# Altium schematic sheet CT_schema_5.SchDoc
size 573 x 363 mm
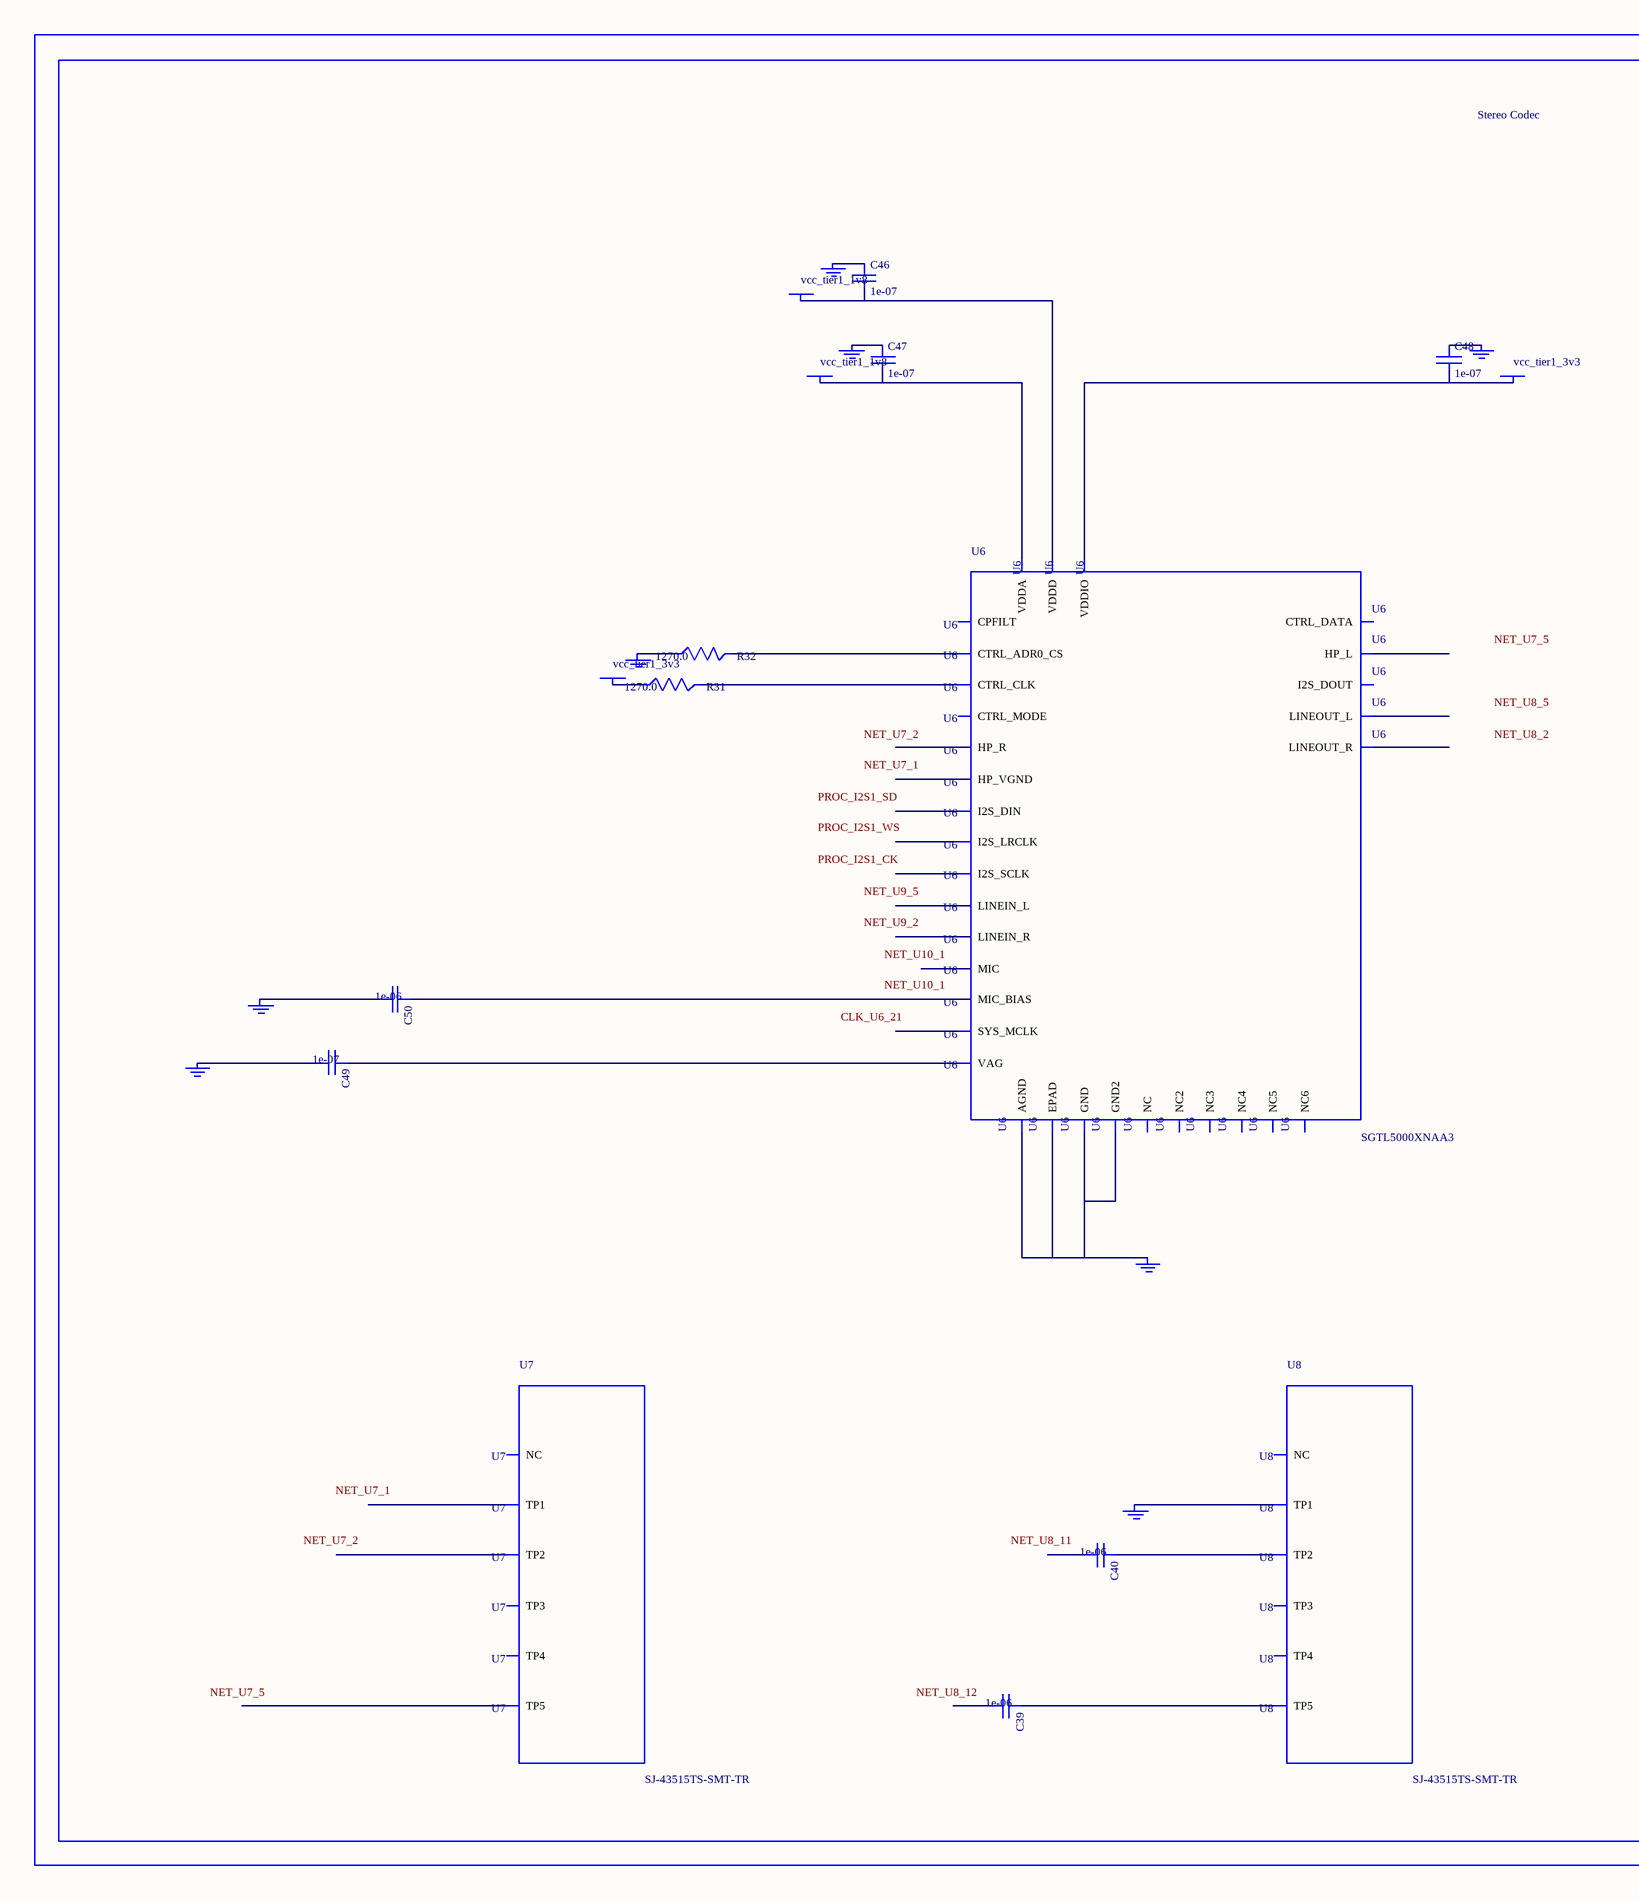
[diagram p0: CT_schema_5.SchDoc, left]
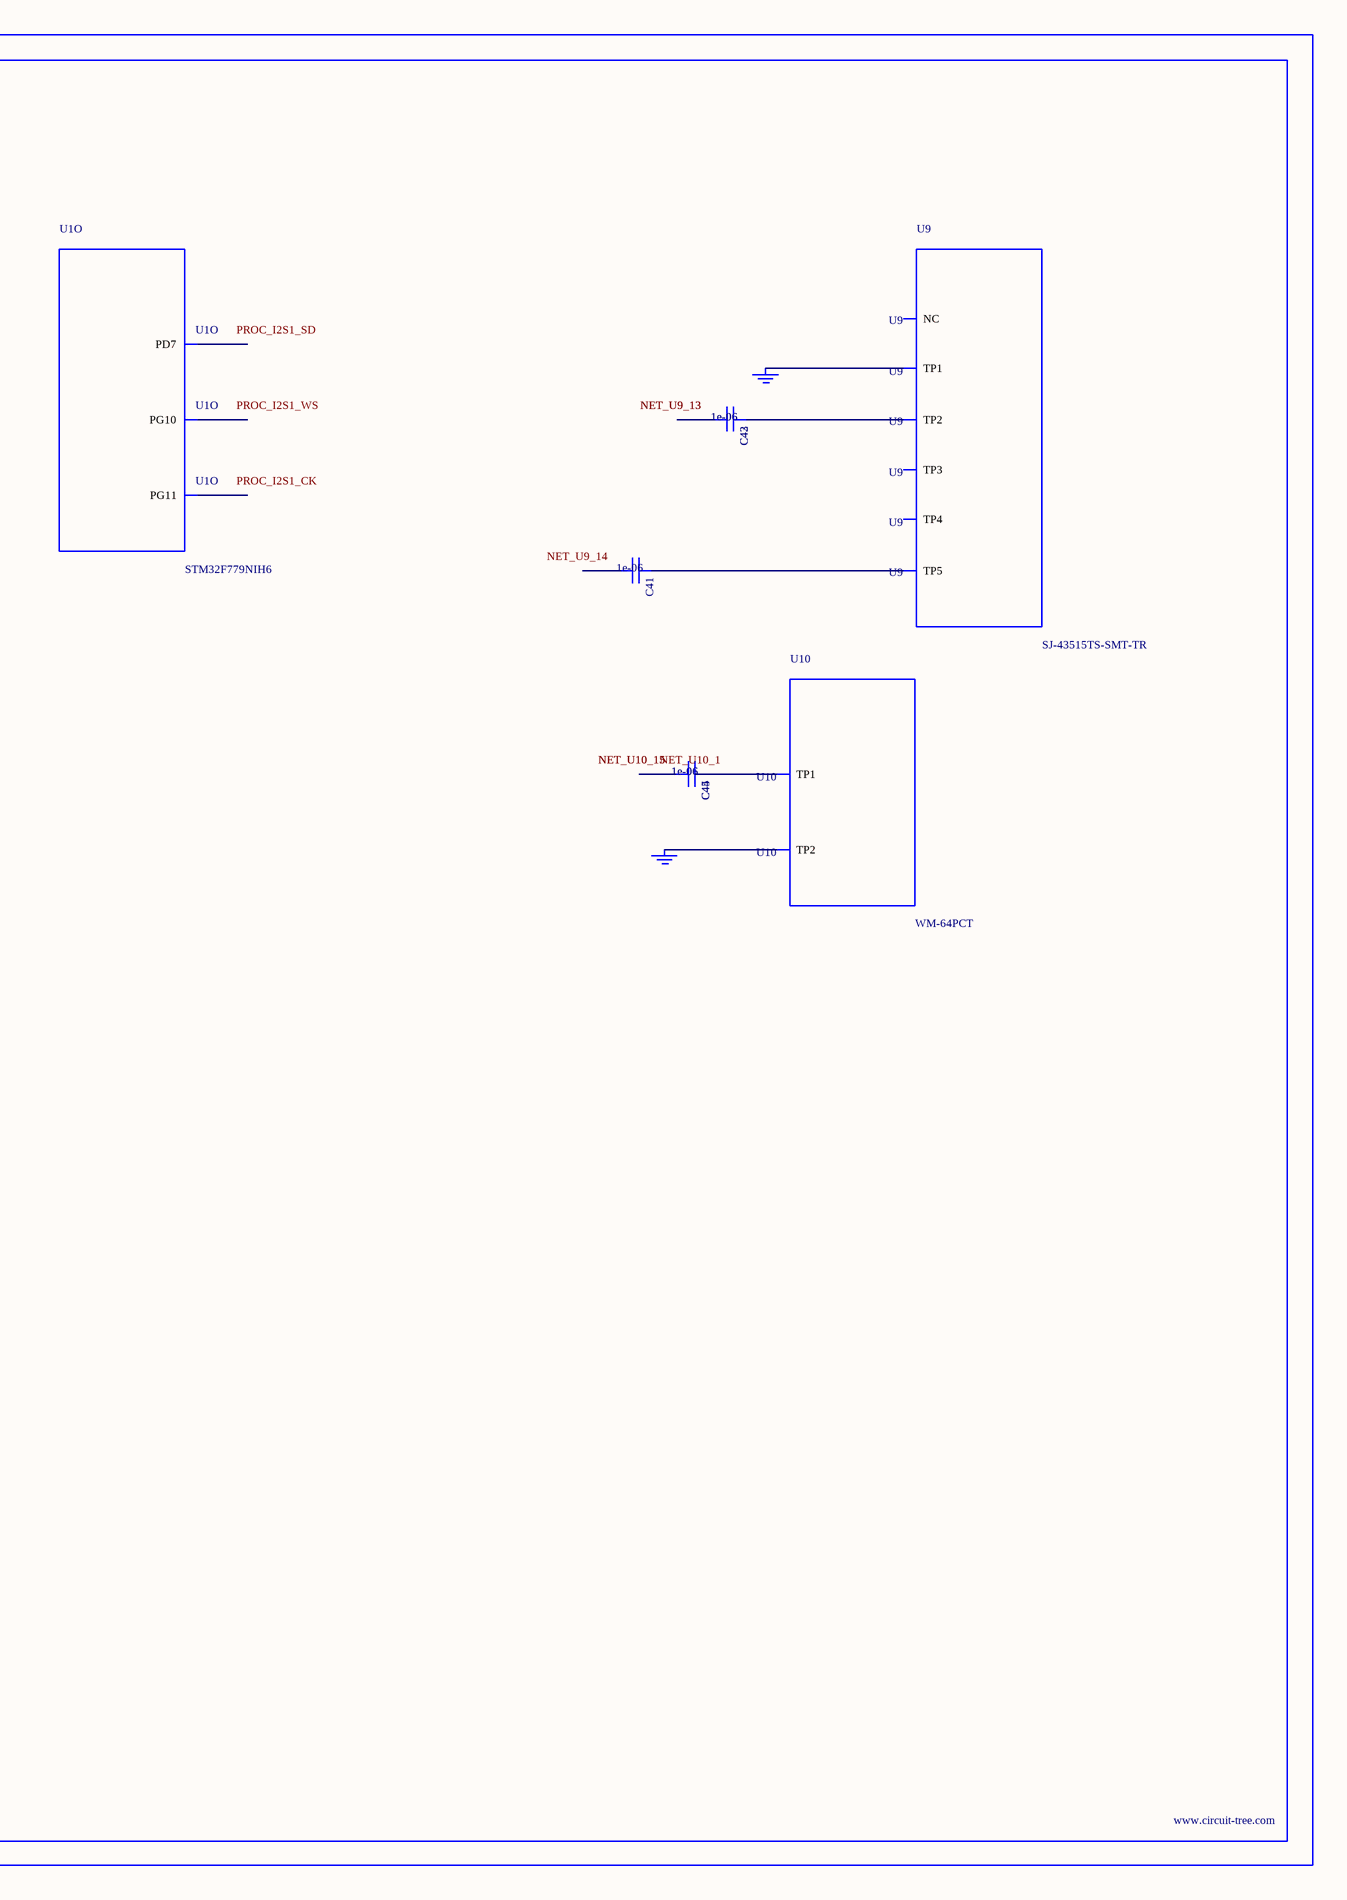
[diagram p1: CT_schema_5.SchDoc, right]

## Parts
BORDER4  (no value)
C39  1e-06  [C0603]
C40  1e-06  [C0603]
C41  1e-06  [C0603]
C42  1e-06  [C0603]
C43  1e-06  [C0603]
C44  1e-06  [C0603]
C45  1e-06  [C0603]
C46  1e-07  [C0402]
C47  1e-07  [C0402]
C48  1e-07  [C0402]
C49  1e-07  [C0402]
C50  1e-06  [C0603]
GND_INSTANCE_4_0  (no value)
GND_INSTANCE_4_1  (no value)
GND_INSTANCE_4_2  (no value)
GND_INSTANCE_4_3  (no value)
GND_INSTANCE_4_4  (no value)
GND_INSTANCE_4_5  (no value)
GND_INSTANCE_4_6  (no value)
GND_INSTANCE_4_7  (no value)
GND_INSTANCE_4_8  (no value)
GND_INSTANCE_4_9  (no value)
GND_INSTANCE_4_10  (no value)
POWER_INSTANCE_4_0  vcc_tier1_1v8
POWER_INSTANCE_4_1  vcc_tier1_3v3
POWER_INSTANCE_4_2  vcc_tier1_3v3
POWER_INSTANCE_4_3  vcc_tier1_1v8
R31  1270.0  [R0603]
R32  1270.0  [R0603]
U1  STM32F779NIH6  [TFBGA216]  (part O of 16)
U6  SGTL5000XNAA3  [QFN-32]
U7  SJ-43515TS-SMT-TR  [SJ-43515TS-SMT-TR]
U8  SJ-43515TS-SMT-TR  [SJ-43515TS-SMT-TR]
U9  SJ-43515TS-SMT-TR  [SJ-43515TS-SMT-TR]
U10  WM-64PCT  [WM-64PC]

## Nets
NetC39_1: C39.1 U8.5(TP5)
NetC40_1: C40.1 U8.2(TP2)
NetC41_1: C41.1 U9.5(TP5)
NetC42_1: C42.1 C43.1 U9.2(TP2)
NetC42_2: C42.2 C43.2
NetC44_1: C44.1 C45.1 U10.1(TP1)
NetC44_2: C44.2 C45.2
NetC46_1: C46.1 GND_INSTANCE_4_5.0(GND)
NetC46_2: C46.2 POWER_INSTANCE_4_3.0(PWR) U6.30(VDDD)
NetC47_1: C47.1 GND_INSTANCE_4_1.0(GND)
NetC47_2: C47.2 POWER_INSTANCE_4_0.0(PWR) U6.5(VDDA)
NetC48_1: C48.1 GND_INSTANCE_4_4.0(GND)
NetC48_2: C48.2 POWER_INSTANCE_4_1.0(PWR) U6.20(VDDIO)
NetC49_1: C49.1 U6.10(VAG)
NetC49_2: C49.2 GND_INSTANCE_4_2.0(GND)
NetC50_1: C50.1 U6.16(MIC_BIAS)
NetC50_2: C50.2 GND_INSTANCE_4_3.0(GND)
NetGND_INSTANCE_4_0_0: GND_INSTANCE_4_0.0(GND) U6.1(GND) U6.3(GND2) U6.7(AGND) U6.EXP(EPAD)
NetGND_INSTANCE_4_6_0: GND_INSTANCE_4_6.0(GND) R32.1
NetGND_INSTANCE_4_7_0: GND_INSTANCE_4_7.0(GND) U8.1(TP1)
NetGND_INSTANCE_4_8_0: GND_INSTANCE_4_8.0(GND) GND_INSTANCE_4_9.0(GND) U9.1(TP1)
NetGND_INSTANCE_4_10_0: GND_INSTANCE_4_10.0(GND) U10.2(TP2)
NetPOWER_INSTANCE_4_2_0: POWER_INSTANCE_4_2.0(PWR) R31.1
NetR31_2: R31.2 U6.29(CTRL_CLK)
NetR32_2: R32.2 U6.31(CTRL_ADR0_CS)

Not connected (* = marked no-connect by the designer): C39 2; C40 2; C41 2; U1 A11(PD7) B8(PG11) C8(PG10); U6 2(HP_R) 4(HP_VGND) 6(HP_L) 8(NC) 9(NC2) 11(LINEOUT_R) 12(LINEOUT_L) 13(LINEIN_R) 14(LINEIN_L) 15(MIC) 17(NC3) 18(CPFILT) 19(NC4) 21(SYS_MCLK) 22(NC5) 23(I2S_LRCLK) 24(I2S_SCLK) 25(I2S_DOUT) 26(I2S_DIN) 27(CTRL_DATA) 28(NC6) 32(CTRL_MODE); U7 1(TP1) 2(TP2) 3(TP3) 4(TP4) 5(TP5) 6(NC); U8 3(TP3) 4(TP4) 6(NC); U9 3(TP3) 4(TP4) 6(NC)

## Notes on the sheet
- Labels drawn without touching a wire or pin: CLK_U6_21, NET_U7_1, NET_U7_2, NET_U7_5, NET_U8_2, NET_U8_5, NET_U8_11, NET_U8_12, NET_U9_2, NET_U9_5, NET_U9_14, NET_U10_1, PROC_I2S1_CK, PROC_I2S1_SD, PROC_I2S1_WS

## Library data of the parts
BORDER4 = BORDER_PAGE4
C39-C45 C50 = C0603C105K3RACTU
C46-C49 = C0402C104K3RACTU
GND_INSTANCE_4_0-GND_INSTANCE_4_10 = GND
POWER_INSTANCE_4_0-POWER_INSTANCE_4_3 = PWR
R31 R32 = RC0603FR-071K27L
